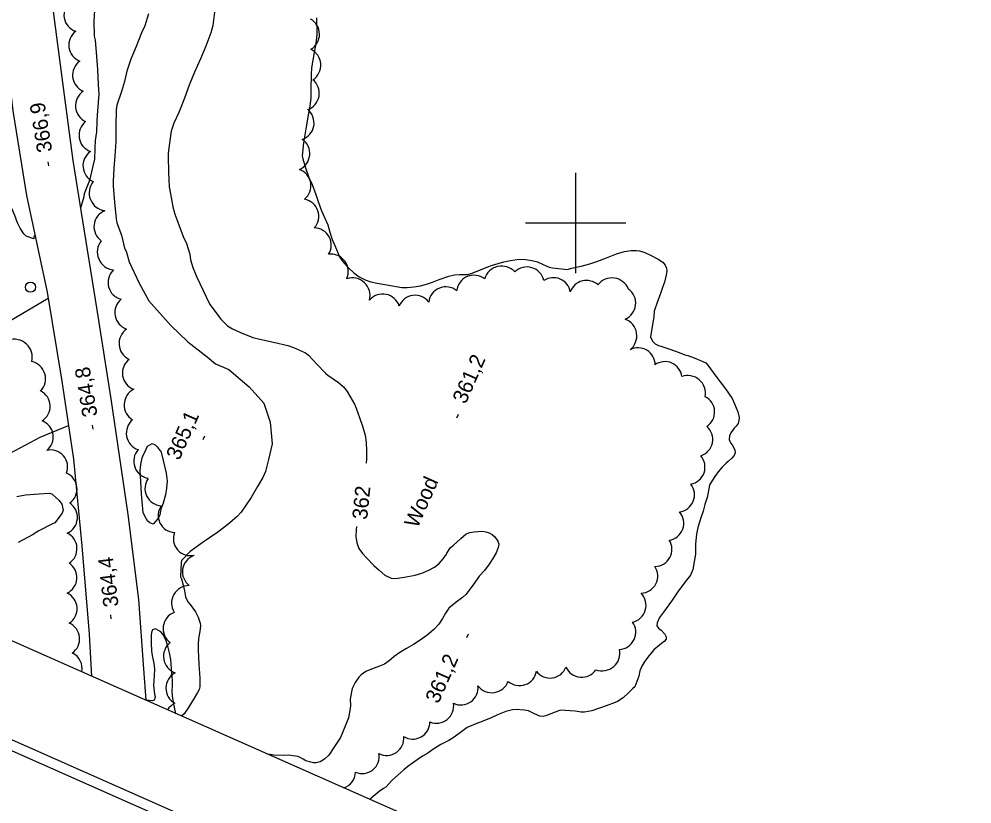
# Model space of a CAD drawing. Extents: x 287698 to 290158, y 5234163 to 5237182.
# Drawn here: x 287889.1 to 288079, y 5234684.2 to 5234840.6 of the extents above; entities that cross this region are included whole.
import ezdxf

# ---------------------------------------------------------------- set-up
doc = ezdxf.new("R2010")
doc.units = 0
for name, color, linetype in [('Niveau 2', 7, 'Continuous'), ('Niveau 21', 7, 'Continuous'), ('Niveau 22', 7, 'Continuous'), ('Niveau 3', 7, 'Continuous'), ('Niveau 36', 7, 'Continuous'), ('Niveau 4', 7, 'Continuous'), ('Niveau 44', 7, 'Continuous'), ('Niveau 60', 7, 'Continuous'), ('Niveau 61', 7, 'Continuous')]:
    doc.layers.add(name, color=color, linetype=linetype)

msp = doc.modelspace()

# ---------------------------------------------------------------- linework, layer by layer
at = {"layer": 'Niveau 2'}
for points in [[(287904.12, 5234842.34), (287903.98, 5234840.24), (287904.09, 5234837.21), (287904.24, 5234836.42), (287904.56, 5234833.17), (287904.72, 5234830.55), (287904.83, 5234827.59), (287904.99, 5234825.66), (287904.66, 5234821.46), (287904.58, 5234820.23), (287904.52, 5234818.16), (287904.25, 5234816.41), (287904.17, 5234814.96), (287904.17, 5234814.86)], [(287928.02, 5234842.01), (287927.69, 5234839.33), (287927.33, 5234837.89), (287926.35, 5234835.24), (287925.28, 5234832.73), (287924.06, 5234830.03), (287923.01, 5234827.43), (287922.07, 5234824.88), (287920.93, 5234822.03), (287919.97, 5234819.85), (287919.44, 5234818.29), (287919.19, 5234816.92), (287918.8, 5234813.89), (287918.79, 5234813.17), (287918.88, 5234810.09), (287919.03, 5234807.17), (287919.31, 5234805.82), (287919.75, 5234803.18), (287920.13, 5234801.76), (287920.93, 5234799.64), (287921.8, 5234797.28), (287922.48, 5234795.91), (287923.11, 5234793.76), (287923.27, 5234792.64), (287923.75, 5234791.09), (287924.51, 5234789.19), (287925.72, 5234786.67), (287927.15, 5234783.72), (287927.55, 5234783.13), (287929.34, 5234780.84), (287930.61, 5234779.52), (287931.61, 5234778.89), (287933.22, 5234778.18), (287935.68, 5234777.2), (287937.11, 5234776.82), (287939.81, 5234776.25), (287942.68, 5234775.58), (287943.77, 5234775.2), (287946.16, 5234774.14), (287946.76, 5234773.66), (287948.48, 5234771.77), (287950.16, 5234770.03), (287950.66, 5234769.67), (287952.76, 5234768.22), (287953.78, 5234767.36), (287954.55, 5234766.33), (287954.55, 5234766.27)], [(287914.89, 5234841.65), (287914.13, 5234839.28), (287913.52, 5234837.88), (287912.42, 5234835.17), (287911.4, 5234832.64), (287910.6, 5234830.26), (287910.14, 5234828.16), (287909.49, 5234826.19), (287908.59, 5234823.45), (287908.45, 5234822.54), (287908.36, 5234819.35), (287908.38, 5234816.19), (287908.18, 5234813.39), (287907.96, 5234810.83), (287907.82, 5234808.31), (287907.88, 5234807.37), (287908.12, 5234804.07), (287908.45, 5234800.81), (287908.6, 5234800.02), (287909.49, 5234797.56), (287910.1, 5234794.94), (287910.42, 5234794.39), (287911.03, 5234792.24), (287913.01, 5234788.01), (287914.97, 5234784.48), (287919.34, 5234779.59), (287922.72, 5234776.33), (287926.57, 5234773.32), (287928.26, 5234771.92), (287930.89, 5234770.79), (287934.99, 5234767.31), (287937.9, 5234764.05), (287939.15, 5234760.27), (287939.53, 5234755.97), (287938.81, 5234752.83), (287938.18, 5234750.48), (287937.68, 5234749.26), (287936.65, 5234747.45), (287935.34, 5234745.26), (287933.34, 5234742.34), (287932.53, 5234741.45), (287930.71, 5234739.89), (287928.68, 5234738.4), (287925.76, 5234736.4), (287923.23, 5234734.5), (287921.5, 5234732.71), (287921.39, 5234732.26), (287921.25, 5234729.47), (287921.45, 5234729.06), (287921.78, 5234727.79)], [(287892.02, 5234796.86), (287890.49, 5234797.39), (287890.05, 5234797.84), (287889.29, 5234798.95), (287888.76, 5234800.05), (287888.22, 5234801.45), (287887.17, 5234803.95), (287886.64, 5234804.95), (287885.81, 5234806.64), (287885.25, 5234808.02), (287885.06, 5234808.78), (287885.05, 5234809.94), (287884.66, 5234810.54), (287884.13, 5234811.72), (287883.01, 5234814.04)], [(287904.17, 5234814.86), (287904.11, 5234812.69), (287903.73, 5234811.03), (287903.11, 5234808.44), (287902.08, 5234805.82), (287901.98, 5234805.17), (287901.34, 5234802.95)], [(287892.26, 5234797.6), (287892.04, 5234797.16), (287892.02, 5234796.86)], [(287954.55, 5234766.27), (287955.94, 5234763.89), (287956.27, 5234763.07), (287956.96, 5234761.22), (287957.63, 5234759.31), (287958.08, 5234757.71), (287958.27, 5234756.23), (287958.35, 5234754.68), (287958.32, 5234753.01), (287958.26, 5234752.15)], [(287913.52, 5234745.98), (287913.39, 5234748.49), (287913.24, 5234750.63), (287913.37, 5234751.86), (287913.61, 5234753.18), (287913.87, 5234753.84), (287914.16, 5234754.31), (287914.72, 5234755.48), (287915.61, 5234756.03), (287916.23, 5234755.78), (287916.63, 5234755.38), (287917.39, 5234754.31), (287917.57, 5234753.81), (287917.84, 5234752.64), (287918.4, 5234750.15), (287918.64, 5234748.51), (287918.5, 5234747.12), (287918.26, 5234745.81), (287917.81, 5234744.13), (287917.37, 5234742.97), (287917.17, 5234741.84), (287916.95, 5234741.34), (287916.63, 5234740.88), (287915.8, 5234739.98), (287915.13, 5234740.22), (287914.69, 5234740.66), (287914.4, 5234741.08), (287913.85, 5234742.25), (287913.52, 5234745.98)], [(287888.64, 5234745.51), (287890.41, 5234745.79), (287893.09, 5234746.03), (287895.13, 5234746.13), (287895.6, 5234746.02), (287897.12, 5234744.66), (287897.6, 5234743.95), (287897.89, 5234742.77), (287897.72, 5234742.17), (287896.21, 5234740.23), (287895.77, 5234740.01), (287893.04, 5234738.61), (287891.8, 5234737.86), (287888.95, 5234736.3)], [(287956.36, 5234739.49), (287956.25, 5234738.85), (287956.21, 5234737.51), (287956.4, 5234736.23), (287956.82, 5234735.11), (287957.52, 5234734.1), (287958.44, 5234733.18), (287959.78, 5234731.73), (287960.84, 5234730.77), (287962.02, 5234729.8), (287963.29, 5234729.21), (287963.95, 5234729.15), (287964.6, 5234729.21), (287965.86, 5234729.41), (287968.01, 5234729.79), (287969.4, 5234730.2), (287970.75, 5234730.79), (287971.87, 5234731.41), (287972.83, 5234732.15), (287973.65, 5234733.07), (287974.26, 5234733.96), (287974.37, 5234734.19)], [(287974.37, 5234734.19), (287975.11, 5234735.29), (287975.61, 5234735.72), (287977.12, 5234737.14), (287978.18, 5234738.04), (287978.94, 5234738.31), (287979.81, 5234738.47), (287981.4, 5234738.57), (287982.14, 5234738.45), (287982.82, 5234738.22), (287983.4, 5234737.89), (287983.89, 5234737.46), (287984.54, 5234736.58), (287984.7, 5234736), (287984.58, 5234735.3), (287984.17, 5234734.27), (287983.51, 5234733.11), (287982.78, 5234732), (287981.85, 5234730.75), (287980.82, 5234729.58), (287979.81, 5234728.15), (287978.11, 5234725.93), (287977.46, 5234725.35), (287976.22, 5234724.41), (287974.75, 5234723.2), (287974.09, 5234722.24), (287973.52, 5234721.14), (287972.79, 5234720.05), (287971.77, 5234718.95), (287970.45, 5234717.85), (287969.07, 5234716.84), (287967.73, 5234715.96), (287966.3, 5234715.22), (287964.98, 5234714.42), (287963.87, 5234713.58), (287962.89, 5234712.73), (287961.9, 5234712.04), (287960.92, 5234711.64), (287959.31, 5234711.08), (287958.22, 5234710.58), (287957.25, 5234709.91), (287956.84, 5234709.45), (287956.1, 5234708.42), (287955.48, 5234707.21), (287955.32, 5234706.53), (287955.12, 5234705.11), (287955.17, 5234703.83), (287955.09, 5234703.22), (287954.73, 5234701.35), (287954.23, 5234700.05), (287953.17, 5234697.46), (287952.77, 5234696.83), (287951.96, 5234695.67), (287950.82, 5234693.94), (287950, 5234693.15), (287949.08, 5234692.59), (287948.29, 5234692.43), (287947.78, 5234692.42), (287947.28, 5234692.51), (287946.23, 5234692.81), (287945.69, 5234693.12), (287944.74, 5234693.64), (287944.16, 5234693.75), (287942.77, 5234693.93), (287941.73, 5234693.86), (287939.89, 5234693.92), (287938.68, 5234694.14), (287938.48, 5234694.17)], [(287921.78, 5234727.79), (287922.06, 5234726.7), (287922.26, 5234725.48), (287922.72, 5234724.49), (287923.19, 5234723.95), (287924.23, 5234722.48), (287924.78, 5234721.43), (287925.21, 5234720.23), (287925.24, 5234719.72), (287925.11, 5234718.58), (287924.87, 5234717.21), (287924.78, 5234716.02), (287924.81, 5234714.88), (287924.95, 5234712.08), (287925.12, 5234709.25), (287925.11, 5234707.55), (287924.96, 5234706.99), (287924.67, 5234706.43), (287923.99, 5234705.29), (287922.72, 5234703.24), (287921.99, 5234702.18), (287921.44, 5234701.72)], [(287920.36, 5234702.2), (287920.28, 5234702.5), (287920.01, 5234703.84), (287919.7, 5234705.69), (287919.62, 5234706.79), (287919.68, 5234707.64), (287919.68, 5234708.91), (287919.56, 5234710.23), (287919.32, 5234713), (287919.09, 5234714.35), (287918.76, 5234715.67), (287918.33, 5234716.92), (287917.73, 5234718.03), (287917.33, 5234718.48), (287916.3, 5234719.08), (287915.71, 5234718.94), (287915.52, 5234718.39), (287915.43, 5234717.76), (287915.4, 5234716.36), (287915.46, 5234714.56), (287915.67, 5234713.44), (287915.98, 5234712.29), (287916.1, 5234711.06), (287916.04, 5234709.74), (287915.89, 5234707.88), (287915.98, 5234707.26), (287916.07, 5234706.11), (287916.19, 5234705.6), (287916.11, 5234704.98), (287916.01, 5234704.9)], [(287916.01, 5234704.9), (287915.64, 5234704.78), (287914.33, 5234704.9)]]:
    msp.add_lwpolyline(points, dxfattribs=at)
at = {"layer": 'Niveau 21'}
for points in [[(287879.89, 5235042.85), (287879.9, 5235022.89), (287880.33, 5235004.18), (287880.73, 5234986.71), (287880.98, 5234968.8), (287881.52, 5234948.64), (287881.54, 5234930.98), (287881.63, 5234911.44), (287882.32, 5234889.66), (287883.09, 5234872.04), (287884.19, 5234855.52), (287885.99, 5234838.36), (287887.83, 5234822.33), (287890.56, 5234805.45)], [(287889.3, 5235042.17), (287889.19, 5235024.7), (287889.22, 5235008.43), (287889.74, 5234987.25), (287890.14, 5234967.08), (287890.75, 5234947.42), (287890.9, 5234930.98), (287891.19, 5234912.55), (287891.76, 5234895.35), (287892.71, 5234877.98), (287894.12, 5234860.95), (287895.48, 5234845.24), (287897.65, 5234828.96), (287899.84, 5234812.47), (287901.74, 5234800.44)], [(287890.56, 5234805.45), (287894.72, 5234786.19), (287897.65, 5234768.46), (287899.94, 5234752.89), (287901.61, 5234735.65), (287903.06, 5234718.06), (287903.56, 5234709.64)], [(287901.74, 5234800.45), (287904.57, 5234782.66), (287907.36, 5234764.95), (287910.79, 5234741.9), (287912.88, 5234724.96), (287913.92, 5234711.13), (287914.33, 5234704.87)]]:
    msp.add_lwpolyline(points, dxfattribs=at)
at = {"layer": 'Niveau 22'}
for points in [[(287894.92, 5234784.97), (287886.62, 5234780.05), (287873.28, 5234772.74), (287858.37, 5234766.51), (287841.3, 5234763.24), (287820.2, 5234761.17), (287801.73, 5234762.01), (287782.18, 5234763.37)], [(287857.2, 5234730.16), (287871.77, 5234744.61), (287885.34, 5234753.08), (287893.27, 5234757.29), (287898.95, 5234759.63)]]:
    msp.add_lwpolyline(points, dxfattribs=at)
at = {"layer": 'Niveau 3'}
for p, q in [((287895.01, 5234811.41), (287894.89, 5234812.2)), ((287976.37, 5234761.17), (287976.69, 5234761.9)), ((287903.86, 5234758.9), (287903.76, 5234759.69)), ((287925.77, 5234756.86), (287926.09, 5234757.59)), ((287907.48, 5234721.08), (287907.4, 5234721.87)), ((287978.37, 5234717.38), (287978.69, 5234718.11))]:
    msp.add_line(p, q, dxfattribs=at)
at = {"layer": 'Niveau 36'}
msp.add_ellipse((287891.38, 5234787.2), major_axis=(0.004, 1), ratio=0.999989, dxfattribs=at)
at = {"layer": 'Niveau 4'}
for points in [[(287948.41, 5234840.89), (287948.43, 5234837.55), (287948.22, 5234835.75)], [(287948.22, 5234835.75), (287947.91, 5234833.97), (287947.4, 5234830.89), (287947.34, 5234829.57), (287947.25, 5234826.57), (287947.26, 5234824.94), (287947.06, 5234823.27), (287946.74, 5234821.45), (287946.27, 5234818.78), (287945.77, 5234815.96), (287945.52, 5234813.39), (287945.66, 5234812.77), (287946.17, 5234810.99), (287946.87, 5234809.05), (287947.48, 5234807.69), (287948.27, 5234805.68), (287948.79, 5234804.04), (287949.38, 5234802.38), (287950.07, 5234800.94), (287950.65, 5234799.59), (287951.03, 5234798.14), (287951.48, 5234796.73), (287952.02, 5234795.48), (287953.04, 5234793.14), (287953.82, 5234792.04), (287954.77, 5234791.02), (287955.83, 5234790.08), (287956.91, 5234789.26), (287958.07, 5234788.69), (287959.23, 5234788.28), (287960.5, 5234788), (287962.38, 5234787.68), (287965.38, 5234787.15), (287966.48, 5234787.13), (287967.75, 5234787.25), (287969.09, 5234787.48), (287970.3, 5234787.8), (287971.5, 5234788.21), (287972.8, 5234788.72), (287974.75, 5234789.41), (287975.86, 5234789.66), (287976.97, 5234789.73), (287978.57, 5234789.74), (287979.18, 5234789.94), (287980.76, 5234790.53), (287982.32, 5234791.17), (287983.47, 5234791.55), (287985.74, 5234792.24), (287987.02, 5234792.51), (287988.75, 5234792.75), (287990.05, 5234792.71), (287991.3, 5234792.52), (287992.45, 5234792.26), (287993.55, 5234791.71), (287994.74, 5234791.19), (287995.42, 5234791.08), (287998.4, 5234790.75), (287999.2, 5234790.96), (288001.14, 5234791.36), (288002.85, 5234791.83), (288004.23, 5234792.31), (288006.18, 5234793.03), (288008.2, 5234793.82), (288009.79, 5234794.32), (288011.11, 5234794.49), (288012.16, 5234794.53), (288012.72, 5234794.44), (288013.83, 5234794.13), (288014.93, 5234793.59), (288016.45, 5234792.79), (288017.38, 5234792.15), (288017.84, 5234791.56), (288018.12, 5234790.97), (288018.19, 5234790.46), (288018.11, 5234789.91), (288017.76, 5234788.22), (288017.33, 5234787.13), (288016.94, 5234785.96), (288016.26, 5234784.16), (288015.67, 5234782.43)], [(288015.67, 5234782.43), (288015.6, 5234781.26), (288015.4, 5234780.13), (288014.96, 5234777.3), (288015.13, 5234776.81), (288015.44, 5234776.35), (288015.87, 5234775.93), (288016.51, 5234775.56), (288017.03, 5234775.41), (288018.82, 5234774.82), (288020.63, 5234774.16), (288021.77, 5234773.7), (288022.4, 5234773.59), (288023.68, 5234773.13), (288024.92, 5234772.59), (288026, 5234772.14), (288026.34, 5234771.68), (288027.97, 5234769.45), (288028.86, 5234768.33), (288029.86, 5234766.94), (288031.19, 5234764.98), (288031.66, 5234763.98), (288032.34, 5234762.36), (288032.59, 5234761.23), (288032.56, 5234760.65), (288032.42, 5234760.06), (288032.03, 5234759.47), (288031.64, 5234759.11), (288030.95, 5234758.18), (288030.71, 5234757.55), (288030.64, 5234756.84), (288030.86, 5234756.2), (288031.22, 5234755.8), (288031.75, 5234754.81), (288031.81, 5234754.2), (288031.62, 5234753.64), (288031.18, 5234753.13), (288030.42, 5234752.46), (288030, 5234752.12), (288029.22, 5234751.34), (288028.44, 5234750.39), (288027.76, 5234749.45), (288026.71, 5234747.8), (288026.61, 5234747.31), (288026.24, 5234745.25), (288025.79, 5234743.89), (288025.47, 5234742.53), (288025.05, 5234741.45), (288024.38, 5234739.32), (288024.14, 5234737.97), (288023.89, 5234736.04), (288023.94, 5234735.42), (288023.89, 5234734.01), (288023.72, 5234732.85), (288023.38, 5234730.9), (288022.9, 5234729.78), (288022.12, 5234728.81), (288020.45, 5234726.62), (288019.42, 5234725.03), (288019.12, 5234724.6), (288017.55, 5234722.44), (288016.71, 5234721.39), (288016.28, 5234720.27), (288016.23, 5234719.72), (288016.54, 5234719.22), (288017.05, 5234718.83), (288017.77, 5234718.04), (288018.06, 5234717.54), (288018.08, 5234717.03), (288017.64, 5234716.55), (288017.15, 5234716.18), (288015.58, 5234714.9), (288014.69, 5234713.82), (288013.83, 5234712.68), (288013.25, 5234711.69), (288012.83, 5234710.71), (288012.6, 5234709.7), (288011.82, 5234707.52), (288011.42, 5234707.21), (288010.56, 5234706.34), (288009.51, 5234705.38), (288008.4, 5234704.62), (288007.91, 5234704.45), (288006.08, 5234703.76), (288003.24, 5234702.74), (288001.81, 5234702.49), (288001.1, 5234702.51), (287999.95, 5234702.69), (287996.97, 5234702.88), (287996.48, 5234702.73), (287994.57, 5234701.94), (287994.08, 5234701.74), (287993.4, 5234701.65), (287992.86, 5234701.68), (287991.8, 5234702.18), (287990.62, 5234702.77), (287989.85, 5234702.87), (287988.16, 5234703.03), (287987.43, 5234702.98), (287986.14, 5234702.62), (287984.42, 5234701.97)], [(287984.42, 5234701.97), (287983.17, 5234701.38), (287981.41, 5234700.62), (287980.14, 5234700.19), (287978.39, 5234699.43), (287977.33, 5234698.67), (287975.81, 5234697.5), (287974.72, 5234696.87), (287973.19, 5234696.04), (287971.55, 5234695.06), (287970.57, 5234694.33), (287969.47, 5234693.72), (287968.44, 5234693.02), (287966.61, 5234691.7), (287965.78, 5234690.98), (287963.47, 5234688.95), (287962.17, 5234687.58), (287961.7, 5234687.31), (287960.87, 5234686.68), (287959.26, 5234685.33), (287958.99, 5234685.1)]]:
    msp.add_lwpolyline(points, dxfattribs=at)
at = {"layer": 'Niveau 44'}
for centre, radius, start, end in [((287945.75, 5234831.45), 3.48, 303.1062, 64.8231), ((287945.47, 5234825.85), 3.46, 289.3769, 50.9809), ((287944.43, 5234819.92), 3.46, 288.9381, 50.639), ((287943.6, 5234813.82), 3.44, 293.3484, 55.4009), ((287943.83, 5234807.4), 3.45, 309.1448, 70.9041), ((287945.38, 5234801.33), 3.45, 317.6358, 79.5348), ((287907.49, 5234799.24), 3.46, 112.5328, 234.1584), ((287908.3, 5234794.21), 3.61, 141.8581, 263.5356), ((287951.24, 5234790.31), 3.47, 335.8031, 97.4067), ((287910.29, 5234788.13), 3.46, 133.8185, 255.6782), ((287985.27, 5234787.87), 3.53, 41.9705, 163.8519), ((287990.32, 5234787.77), 3.45, 12.543, 134.5494), ((287955.49, 5234785.5), 3.56, 345.7531, 107.7577), ((287979.75, 5234786.13), 3.45, 52.0014, 173.8225), ((287995.59, 5234785.67), 3.42, 10.1744, 123.7338), ((288007.28, 5234785.54), 3.5, 21.4322, 143.1557), ((287974.16, 5234783.82), 3.44, 51.0808, 173.1932), ((288002.18, 5234785.1), 3.43, 47.7544, 159.9307), ((288008.55, 5234784.01), 3.45, 292.6024, 54.6333), ((287911.64, 5234782.12), 3.46, 129.6923, 251.4771), ((287961.58, 5234782.37), 3.46, 17.9398, 139.5518), ((287968.02, 5234782.2), 3.39, 36.7656, 158.5643), ((287912.47, 5234775.96), 3.46, 123.9128, 245.5673), ((288012.48, 5234771.7), 3.4, 359.7866, 118.1943), ((287913.15, 5234770.08), 3.45, 127.6959, 249.8253), ((287913.52, 5234763.75), 3.47, 116.8186, 238.8343), ((287913.94, 5234758.11), 3.47, 129.6252, 251.2889), ((288018.14, 5234740.15), 3.43, 279.3715, 41.2179)]:
    msp.add_arc(centre, radius, start, end, dxfattribs=at)
for centre, major_axis, ratio, start_param, end_param in [((287901.51, 5234841.48), (-3.44, -0.45), 0.998685, 5.270856, 7.396762), ((287945.52, 5234837.6), (3.45, 0.05), 0.999995, 5.216516, 7.344904), ((287902.49, 5234835.45), (-3.45, -0.44), 0.991901, 5.234547, 7.347714), ((287903.23, 5234829.45), (-3.45, -0.43), 0.993682, 5.216093, 7.33472), ((287903.81, 5234823.37), (-3.46, -0.29), 0.99824, 5.214447, 7.342405), ((287904.52, 5234817.5), (-3.43, -0.55), 0.999733, 5.221115, 7.343927), ((287905.31, 5234811.41), (-3.46, -0.37), 0.989902, 5.21278, 7.325546), ((287906.64, 5234805.99), (-3.33, -1.31), 0.999586, 5.22093, 7.345336), ((287947.9, 5234795.59), (3.01, 1.63), 0.999994, 5.220121, 7.349015), ((288008.66, 5234777.49), (3.55, 0.26), 0.999529, 5.310061, 7.433505), ((287888.12, 5234773.2), (2.9, 2.16), 0.999895, 5.406274, 7.532076), ((287890.88, 5234768.94), (3.35, 1), 0.999979, 5.221718, 7.347287), ((288017.81, 5234768.97), (-3.16, 1.24), 0.999984, 3.633444, 5.705167), ((288022.38, 5234766.08), (-3.3, -1.18), 0.999984, 2.595375, 4.720025), ((287891.87, 5234763.44), (3.42, 0.18), 0.998739, 5.221169, 7.343024), ((288024.35, 5234762.31), (3.38, 0.19), 0.999909, 5.2198, 7.350188), ((287892.51, 5234757.34), (3.39, 0.31), 0.998968, 5.283567, 7.409163), ((288023.93, 5234756.86), (-1.1, 3.24), 0.999995, 3.116064, 5.245223), ((287895.41, 5234751.37), (-2.25, 2.54), 0.991754, 3.632196, 5.792582), ((287915.42, 5234752.52), (-3.27, -1.15), 0.999733, 5.219402, 7.344226), ((288022.39, 5234751.32), (3.23, -1.13), 0.99995, 5.218132, 7.34527), ((287897.31, 5234746.99), (-0.36, 3.37), 0.983909, 3.633255, 5.791522), ((287917.65, 5234747.09), (-3.12, -1.5), 0.99823, 5.215554, 7.342048), ((288020.3, 5234745.81), (3.17, -1.29), 0.999994, 5.222119, 7.34428), ((287897.28, 5234741.32), (3.43, -0.29), 0.999647, 5.219887, 7.346456), ((287920.29, 5234741.74), (-3.13, -1.52), 0.98512, 5.2385, 7.343604), ((287897.22, 5234735.08), (3.42, 0.21), 0.999911, 5.220329, 7.348123), ((287923.27, 5234737.11), (-2.78, -2.02), 0.989765, 5.29204, 7.44286), ((288015.79, 5234734.96), (3, -1.65), 0.99995, 5.220789, 7.342372), ((287925.1, 5234730.47), (-0.53, -3.4), 0.999244, 3.638406, 5.786372), ((287897.2, 5234729.32), (3.38, -0.6), 0.999683, 5.332633, 7.454902), ((288012.96, 5234729.63), (-0.21, 3.42), 0.999995, 3.117641, 5.244022), ((287897.23, 5234723.11), (-3.09, 1.48), 0.999983, 2.594553, 4.722355), ((287923, 5234724.22), (-3.06, 1.73), 0.997875, 5.219174, 7.342795), ((288010.63, 5234723.8), (-0.82, 3.33), 0.999995, 3.114616, 5.244053), ((287921.29, 5234719.16), (-3.31, 1.08), 0.999887, 5.406382, 7.531374), ((287897.75, 5234717.1), (3.42, 0.16), 0.998651, 5.272066, 7.399881), ((288008.54, 5234718.44), (3.13, -1.49), 0.999864, 5.223437, 7.348063), ((287921.41, 5234713.63), (-3.49, -0.53), 0.993289, 5.236128, 7.349823), ((288005.31, 5234714.27), (2.3, -2.68), 0.999743, 5.218024, 7.346558), ((287898.24, 5234711.21), (3.42, -0.08), 0.999492, 6.100631, 7.435644), ((287994.93, 5234712.69), (0.47, -3.36), 0.999994, 5.220246, 7.347553), ((288001.23, 5234712.89), (-0.57, -3.39), 0.999384, 5.303239, 7.425299), ((287921.85, 5234707.3), (-3.47, 0.02), 0.999652, 5.220219, 7.344187), ((287988.84, 5234711.22), (1.15, -3.23), 0.99995, 5.221666, 7.344505), ((287977.16, 5234707.36), (1.99, -2.78), 0.999994, 5.216233, 7.347804), ((287983.32, 5234709.88), (0.52, -3.46), 0.99826, 5.218658, 7.344391), ((287921.67, 5234701.18), (-3.45, 0.27), 0.996438, 5.247705, 5.828084), ((287972.3, 5234703.72), (-0.53, 3.39), 0.999984, 2.590534, 4.721278), ((287967.55, 5234700.55), (1.08, -3.25), 0.999883, 5.408015, 7.531486), ((287962.37, 5234697.28), (2.8, 1.93), 0.999937, 3.636515, 5.788263), ((287957.49, 5234693.66), (1.38, -3.1), 0.99921, 5.460848, 7.618115), ((287952.69, 5234690.68), (0.79, -3.38), 0.999929, 0.097189, 1.301234)]:
    msp.add_ellipse(centre, major_axis=major_axis, ratio=ratio, start_param=start_param, end_param=end_param, dxfattribs=at)
at = {"layer": 'Niveau 60'}
for points in [[(289088.15, 5234163.34), (287698.12, 5234778.71), (288762.01, 5237181.96), (290152.07, 5236566.6), (289088.15, 5234163.34)], [(289087.13, 5234165.98), (287700.76, 5234779.73), (288763.06, 5237179.33), (290149.43, 5236565.58), (289087.13, 5234165.98)]]:
    msp.add_lwpolyline(points, dxfattribs=at)
msp.add_lwpolyline([(289077.96, 5234189.73), (287724.51, 5234788.9), (288562.53, 5236681.9), (289915.99, 5236082.74)], close=True, dxfattribs=at)
at = {"layer": 'Niveau 61'}
for points in [[(288000, 5234810), (288000, 5234800), (288000, 5234790)], [(287990, 5234800), (288000, 5234800), (288010, 5234800)]]:
    msp.add_lwpolyline(points, dxfattribs=at)

# ---------------------------------------------------------------- texts
at = {"layer": 'Niveau 2'}
msp.add_text('362', height=3, rotation=84.1769, dxfattribs=at).set_placement((287958.46, 5234740.78))
at = {"layer": 'Niveau 3'}
for s, rotation, p in [('366,9', 99.1348, (287895.73, 5234814.3)), ('361,2', 66.1217, (287978.09, 5234763.75)), ('364,8', 99.3188, (287904.75, 5234761.59)), ('365,1', 66.1217, (287921.01, 5234752.52)), ('364,4', 96.6377, (287908.94, 5234723.62)), ('361,2', 66.1217, (287972.67, 5234704.04))]:
    msp.add_text(s, height=3, rotation=rotation, dxfattribs=at).set_placement(p)
at = {"layer": 'Niveau 44'}
msp.add_text('Wood', height=3, rotation=66.1212, dxfattribs=at).set_placement((287968.5, 5234738.99))

doc.saveas('drawing.dxf')
